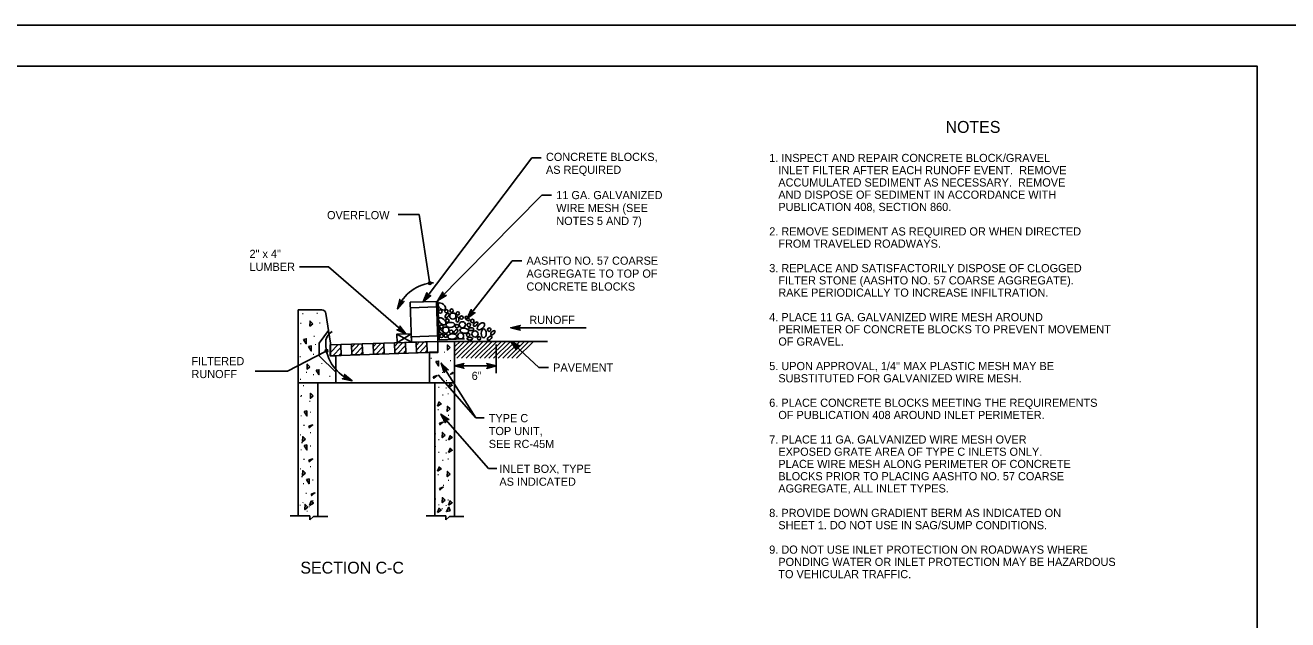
# Model space of a CAD drawing. Extents: x 636183 to 639890, y 299162 to 300538.
# Drawn here: x 637676.7 to 638140.2, y 300320 to 300538.4 of the extents above; entities that cross this region are included whole.
import ezdxf

# ---------------------------------------------------------------- set-up
doc = ezdxf.new("R2010")
doc.units = 0
for name, color, linetype in [('1', 7, 'Continuous'), ('Default', 7, 'Continuous'), ('PLT-BNDY', 7, 'Continuous')]:
    doc.layers.add(name, color=color, linetype=linetype)

# ---------------------------------------------------------------- blocks, each defined once
blk = doc.blocks.new('SC9446')
at = {"layer": 'Default'}
blk.add_line((0, 0), (0, 0), dxfattribs=at)

msp = doc.modelspace()

# ---------------------------------------------------------------- linework, layer by layer
at = {"layer": '1'}
msp.add_lwpolyline([(638128.91, 299959.45), (638128.91, 300523.45), (637342.91, 300523.45), (637342.91, 299959.45), (638128.91, 299959.45), (638128.91, 299985.81), (637928.91, 299985.81), (637928.91, 300050.49), (638128.91, 300050.49), (638128.91, 300079.45), (637928.91, 300079.45), (637928.91, 299959.45), (638007.72, 299959.45), (638007.72, 299985.81), (638007.72, 299959.45), (638084.72, 299959.45), (638084.72, 299985.81), (638084.72, 299973.49), (638128.91, 299973.49)], dxfattribs=at)
at = {"layer": 'Default'}
for p, q in [((637822.84, 300436.83), (637862.62, 300489.75)), ((637866.12, 300489.75), (637862.62, 300489.75)), ((637828.18, 300437.25), (637866.4, 300476.04)), ((637869.9, 300476.04), (637866.4, 300476.04)), ((637813.6, 300468.88), (637821.36, 300468.88)), ((637821.36, 300468.88), (637825.14, 300444.17)), ((637777.33, 300449.7), (637787.97, 300449.7)), ((637816.37, 300425), (637787.97, 300449.7)), ((637838.96, 300430.69), (637855.46, 300451.94)), ((637858.96, 300451.94), (637855.46, 300451.94)), ((637827.75, 300434.97), (637818.06, 300434.67)), ((637828.18, 300437.25), (637828.67, 300422.8)), ((637776.95, 300407.1), (637776.95, 300433.84)), ((637776.95, 300433.84), (637785.57, 300433.84)), ((637787.08, 300432.54), (637788.72, 300421.61)), ((637784.59, 300421.61), (637788.03, 300426.24)), ((637788.03, 300426.24), (637788.03, 300426.24)), ((637784.59, 300421.61), (637784.59, 300417.03)), ((637788.59, 300421.03), (637828.15, 300422.29)), ((637788.69, 300418.06), (637791.56, 300421.13)), ((637788.72, 300421.61), (637788.72, 300417.03)), ((637796.53, 300419.98), (637797.8, 300421.33)), ((637796.58, 300418.31), (637799.46, 300421.38)), ((637804.43, 300420.23), (637805.69, 300421.58)), ((637804.48, 300418.56), (637807.36, 300421.63)), ((637812.33, 300420.48), (637813.59, 300421.83)), ((637812.38, 300418.81), (637815.26, 300421.88)), ((637813.1, 300424.89), (637818.46, 300421.98)), ((637818.36, 300425.06), (637813.2, 300421.81)), ((637813.48, 300417.82), (637816.27, 300420.79)), ((637828.09, 300424.3), (637818.4, 300423.99)), ((637820.23, 300420.73), (637821.49, 300422.08)), ((637820.28, 300419.06), (637823.16, 300422.13)), ((637821.38, 300418.07), (637824.17, 300421.04)), ((637828.67, 300422.8), (637837.98, 300423.18)), ((637834.26, 300422.29), (637868.43, 300422.29)), ((637834.58, 300417.17), (637839.7, 300422.29)), ((637834.58, 300418.85), (637838.01, 300422.29)), ((637834.58, 300420.54), (637836.33, 300422.29)), ((637835.17, 300416.07), (637841.39, 300422.29)), ((637836.86, 300416.07), (637843.08, 300422.29)), ((637838.55, 300416.07), (637844.77, 300422.29)), ((637840.23, 300416.07), (637846.46, 300422.29)), ((637841.92, 300416.07), (637848.15, 300422.29)), ((637843.61, 300416.07), (637849.83, 300422.29)), ((637845.26, 300416.07), (637851.48, 300422.29)), ((637846.94, 300416.07), (637853.17, 300422.29)), ((637848.63, 300416.07), (637854.85, 300422.29)), ((637849.62, 300421.16), (637849.62, 300410.55)), ((637850.32, 300416.07), (637856.54, 300422.29)), ((637852.01, 300416.07), (637858.23, 300422.29)), ((637853.7, 300416.07), (637859.92, 300422.29)), ((637854.93, 300422.29), (637865.25, 300412.69)), ((637855.39, 300416.07), (637861.61, 300422.29)), ((637857.08, 300416.07), (637863.3, 300422.29)), ((637786.9, 300418.59), (637772.96, 300411.33)), ((637784.59, 300417.03), (637790.71, 300410.92)), ((637788.72, 300417.03), (637828.15, 300418.28)), ((637789.78, 300417.06), (637792.58, 300420.04)), ((637790.71, 300410.92), (637790.71, 300417.03)), ((637791.88, 300417.13), (637792.64, 300417.95)), ((637797.68, 300417.31), (637800.47, 300420.29)), ((637799.77, 300417.38), (637800.54, 300418.2)), ((637805.58, 300417.56), (637808.37, 300420.54)), ((637807.67, 300417.63), (637808.44, 300418.45)), ((637815.57, 300417.88), (637816.34, 300418.7)), ((637823.47, 300418.13), (637824.24, 300418.95)), ((637829.41, 300414.29), (637842.14, 300394.17)), ((637868.75, 300412.69), (637865.25, 300412.69)), ((637761.13, 300411.3), (637772.96, 300411.33)), ((637790.71, 300407.1), (637776.95, 300407.1)), ((637776.95, 300358.4), (637776.95, 300407.1)), ((637784.12, 300358.11), (637784.12, 300407.1)), ((637790.71, 300410.92), (637790.71, 300407.1)), ((637790.71, 300407.1), (637825.09, 300407.1)), ((637827.1, 300358.4), (637827.1, 300407.1)), ((637828.3, 300410.01), (637842.14, 300394.17)), ((637829.29, 300395.58), (637846.79, 300375.56)), ((637845.14, 300394.17), (637842.14, 300394.17)), ((637777.91, 300387.97), (637777.74, 300387.91)), ((637777.91, 300375.5), (637777.74, 300375.45)), ((637849.79, 300375.56), (637846.79, 300375.56)), ((637778.75, 300363.04), (637778.58, 300362.98)), ((637773.97, 300358.21), (637781.14, 300358.21)), ((637781.14, 300358.21), (637781.14, 300356.71)), ((637781.14, 300356.71), (637782.51, 300357.92)), ((637782.51, 300357.92), (637787.76, 300357.92)), ((637831.06, 300358.21), (637831.06, 300356.71)), ((637831.06, 300356.71), (637832.44, 300357.92)), ((637832.44, 300357.92), (637837.69, 300357.92))]:
    msp.add_line(p, q, dxfattribs=at)
for points in [[(637825.25, 300439.07), (637825.59, 300439.16), (637822.84, 300436.83), (637825.25, 300439.07), (637824.83, 300439.13), (637822.84, 300436.83), (637824.4, 300439.43), (637824.2, 300439.8), (637822.84, 300436.83), (637824.16, 300440.18), (637824.2, 300439.8)], [(637830.89, 300439.13), (637831.24, 300439.17), (637828.18, 300437.25), (637830.89, 300439.13), (637830.49, 300439.25), (637828.18, 300437.25), (637830.11, 300439.61), (637829.96, 300440), (637828.18, 300437.25), (637829.98, 300440.38), (637829.96, 300440)], [(637815.41, 300436.82), (637815.73, 300436.96), (637813.39, 300434.21), (637815.41, 300436.82), (637814.99, 300436.81), (637813.39, 300434.21), (637814.52, 300437.04), (637814.26, 300437.37), (637813.39, 300434.21), (637814.16, 300437.73), (637814.26, 300437.37)], [(637841.48, 300432.8), (637841.83, 300432.87), (637838.96, 300430.69), (637841.48, 300432.8), (637841.07, 300432.88), (637838.96, 300430.69), (637840.66, 300433.21), (637840.48, 300433.59), (637838.96, 300430.69), (637840.46, 300433.96), (637840.48, 300433.59)], [(637814.31, 300427.56), (637814.24, 300427.9), (637816.37, 300425), (637814.31, 300427.56), (637814.22, 300427.15), (637816.37, 300425), (637813.89, 300426.74), (637813.5, 300426.57), (637816.37, 300425), (637813.13, 300426.56), (637813.5, 300426.57)], [(637858.18, 300426.63), (637858.45, 300426.41), (637854.95, 300427.27), (637858.18, 300426.63), (637857.98, 300427), (637854.95, 300427.27), (637857.98, 300427.53), (637858.16, 300427.9), (637854.95, 300427.27), (637858.44, 300428.16), (637858.16, 300427.9)], [(637854.95, 300427.27), (637882.64, 300427.26)], [(637825.15, 300418.23), (637828.21, 300418.23), (637828.21, 300421.29)], [(637828.12, 300421.25), (637828.21, 300418.28)], [(637856.89, 300419.64), (637856.94, 300419.3), (637854.93, 300422.29), (637856.89, 300419.64), (637857, 300420.05), (637854.93, 300422.29), (637857.35, 300420.44), (637857.73, 300420.6), (637854.93, 300422.29), (637858.11, 300420.6), (637857.73, 300420.6)], [(637790.71, 300417.02), (637788.63, 300417.02), (637788.63, 300420.08)], [(637830.57, 300411.21), (637830.52, 300410.86), (637829.41, 300414.29), (637830.57, 300411.21), (637830.78, 300411.57), (637829.41, 300414.29), (637831.22, 300411.86), (637831.64, 300411.9), (637829.41, 300414.29), (637832, 300411.79), (637831.64, 300411.9)], [(637837.5, 300412.62), (637837.77, 300412.4), (637834.26, 300413.26), (637837.5, 300412.62), (637837.3, 300412.99), (637834.26, 300413.26), (637837.29, 300413.52), (637837.48, 300413.89), (637834.26, 300413.26), (637837.76, 300414.15), (637837.48, 300413.89)], [(637849.62, 300413.26), (637834.26, 300413.26)], [(637846.39, 300413.9), (637846.12, 300414.12), (637849.62, 300413.26), (637846.39, 300413.9), (637846.58, 300413.52), (637849.62, 300413.26), (637846.59, 300413), (637846.41, 300412.62), (637849.62, 300413.26), (637846.12, 300412.37), (637846.41, 300412.62)], [(637794.04, 300409.81), (637793.9, 300410.13), (637796.67, 300407.82), (637794.04, 300409.81), (637794.06, 300409.39), (637796.67, 300407.82), (637793.83, 300408.92), (637793.5, 300408.66), (637796.67, 300407.82), (637793.14, 300408.55), (637793.5, 300408.66)], [(637834.26, 300407.1), (637834.26, 300358.11)], [(637830.94, 300392.74), (637830.95, 300392.39), (637829.29, 300395.58), (637830.94, 300392.74), (637831.09, 300393.13), (637829.29, 300395.58), (637831.48, 300393.48), (637831.89, 300393.59), (637829.29, 300395.58), (637832.26, 300393.55), (637831.89, 300393.59)], [(637831.06, 300358.21), (637823.9, 300358.21)]]:
    msp.add_lwpolyline(points, dxfattribs=at)
for points in [[(637817.99, 300436.67), (637818.46, 300421.98), (637828.15, 300422.29), (637827.68, 300436.98)], [(637782.23, 300428.78), (637781.2, 300427.89), (637781.25, 300429.74)], [(637778.85, 300423), (637779.85, 300423.23), (637779.88, 300421.4)], [(637788.59, 300421.03), (637788.72, 300417.03), (637792.67, 300417.15), (637792.54, 300421.16)], [(637796.49, 300421.28), (637796.62, 300417.28), (637800.57, 300417.41), (637800.44, 300421.41)], [(637804.39, 300421.53), (637804.52, 300417.53), (637808.46, 300417.66), (637808.34, 300421.66)], [(637812.29, 300421.79), (637812.41, 300417.78), (637816.36, 300417.91), (637816.24, 300421.91)], [(637818.46, 300421.98), (637818.36, 300425.06), (637813.1, 300424.89), (637813.2, 300421.81)], [(637820.18, 300422.04), (637820.31, 300418.03), (637824.26, 300418.16), (637824.13, 300422.16)], [(637834.26, 300407.1), (637825.09, 300407.1), (637825.09, 300418.28), (637828.15, 300418.28), (637828.15, 300422.29), (637834.26, 300422.29)], [(637832.7, 300419.99), (637831.67, 300419.1), (637831.71, 300420.96)], [(637780.67, 300420.37), (637781.67, 300420.6), (637781.7, 300418.77)], [(637781.22, 300412.99), (637780.19, 300412.1), (637780.24, 300413.95)], [(637783.5, 300411.66), (637784.5, 300411.89), (637784.53, 300410.07)], [(637827.42, 300414.84), (637828.41, 300415.07), (637828.45, 300413.25)], [(637826.44, 300409.3), (637826.68, 300408.74), (637827.86, 300409.77)], [(637832.09, 300405.33), (637833.47, 300406.19), (637832.69, 300406.89)], [(637832.09, 300405.33), (637833.47, 300406.19), (637832.69, 300406.89)], [(637833.8, 300410.54), (637833.64, 300410.91), (637832.85, 300410.23)], [(637782.44, 300402.26), (637781.4, 300401.37), (637781.45, 300403.22)], [(637828.06, 300398.46), (637829.43, 300399.32), (637828.65, 300400.02)], [(637828.06, 300398.46), (637829.43, 300399.32), (637828.65, 300400.02)], [(637832.65, 300397.45), (637831.62, 300396.56), (637831.66, 300398.41)], [(637832.65, 300397.45), (637831.62, 300396.56), (637831.66, 300398.41)], [(637779.05, 300396.48), (637780.05, 300396.71), (637780.08, 300394.88)], [(637780.8, 300391.09), (637781.04, 300390.55), (637782.22, 300391.57)], [(637828.73, 300392.18), (637828.97, 300391.63), (637830.15, 300392.65)], [(637828.73, 300392.18), (637828.97, 300391.63), (637830.15, 300392.65)], [(637830.82, 300387.86), (637829.79, 300386.96), (637829.84, 300388.82)], [(637830.82, 300387.86), (637829.79, 300386.96), (637829.84, 300388.82)], [(637779.57, 300386.34), (637778.54, 300385.44), (637778.59, 300387.3)], [(637779.05, 300384.01), (637780.05, 300384.24), (637780.08, 300382.42)], [(637832.09, 300386.07), (637833.47, 300386.93), (637832.69, 300387.63)], [(637832.09, 300386.07), (637833.47, 300386.93), (637832.69, 300387.63)], [(637780.8, 300378.63), (637781.04, 300378.08), (637782.22, 300379.1)], [(637832.09, 300381.4), (637833.47, 300382.26), (637832.69, 300382.96)], [(637832.09, 300381.4), (637833.47, 300382.26), (637832.69, 300382.96)], [(637832.09, 300381.4), (637833.47, 300382.26), (637832.69, 300382.96)], [(637779.57, 300373.87), (637778.54, 300372.97), (637778.59, 300374.83)], [(637828.06, 300374.54), (637829.43, 300375.4), (637828.65, 300376.09)], [(637828.06, 300374.54), (637829.43, 300375.4), (637828.65, 300376.09)], [(637828.06, 300374.54), (637829.43, 300375.4), (637828.65, 300376.09)], [(637832.65, 300373.52), (637831.62, 300372.63), (637831.66, 300374.49)], [(637832.65, 300373.52), (637831.62, 300372.63), (637831.66, 300374.49)], [(637832.65, 300373.52), (637831.62, 300372.63), (637831.66, 300374.49)], [(637779.89, 300371.54), (637780.89, 300371.77), (637780.92, 300369.95)], [(637781.63, 300366.16), (637781.87, 300365.61), (637783.05, 300366.63)], [(637828.73, 300368.25), (637828.97, 300367.7), (637830.15, 300368.73)], [(637828.73, 300368.25), (637828.97, 300367.7), (637830.15, 300368.73)], [(637828.73, 300368.25), (637828.97, 300367.7), (637830.15, 300368.73)], [(637780.41, 300361.4), (637779.38, 300360.51), (637779.42, 300362.36)], [(637781.1, 300362.02), (637782.48, 300362.88), (637781.7, 300363.58)], [(637828.06, 300359.42), (637829.43, 300360.28), (637828.65, 300360.98)], [(637830.82, 300363.93), (637829.79, 300363.03), (637829.84, 300364.89)], [(637830.82, 300363.93), (637829.79, 300363.03), (637829.84, 300364.89)], [(637830.82, 300363.93), (637829.79, 300363.03), (637829.84, 300364.89)], [(637832.64, 300360.01), (637831.3, 300359.75), (637832.26, 300361.34)], [(637832.09, 300362.14), (637833.47, 300363), (637832.69, 300363.7)], [(637832.09, 300362.14), (637833.47, 300363), (637832.69, 300363.7)], [(637832.09, 300362.14), (637833.47, 300363), (637832.69, 300363.7)]]:
    msp.add_lwpolyline(points, close=True, dxfattribs=at)
for centre, radius in [((637825.21, 300443.7), 0.481), ((637829.08, 300433.25), 0.63), ((637831.31, 300433.35), 0.63), ((637831.66, 300429.92), 0.63), ((637833.68, 300431.56), 1.14), ((637833.21, 300433.56), 0.63), ((637835.48, 300432.57), 0.63), ((637836.84, 300431.03), 0.63), ((637840.84, 300429.79), 0.63), ((637829.52, 300427.69), 0.63), ((637831.11, 300426.42), 1.14), ((637833.06, 300425.78), 0.63), ((637835.17, 300427.89), 0.63), ((637836.5, 300424.3), 1.14), ((637837.15, 300428.38), 1.14), ((637839.54, 300428.32), 0.63), ((637841.84, 300424.98), 1.14), ((637847.05, 300426.6), 0.63), ((637829.52, 300424.3), 0.63), ((637831.05, 300424.36), 0.63), ((637839.31, 300424.67), 0.63), ((637843.31, 300423.43), 0.63), ((637787.32, 300418.82), 0.481)]:
    msp.add_circle(centre, radius, dxfattribs=at)
for centre, radius, start, end in [((637827.39, 300428.88), 14.98, 93.095, 159.1494), ((637785.57, 300432.31), 1.53, 8.5302, 90), ((637791.53, 300421.91), 4.53, 117.9934, 185.7686), ((637801.99, 300421.82), 14.98, 181.3993, 249.1745)]:
    msp.add_arc(centre, radius, start, end, dxfattribs=at)
for centre, major_axis, ratio in [((637829.64, 300435.1), (1.2, -1.12), 0.565936), ((637829.78, 300429.68), (1.2, -1.12), 0.565936), ((637831.58, 300431.76), (0.688, 0.736), 0.5), ((637835.37, 300430.36), (-0.03, 1.01), 0.5), ((637838.96, 300430.69), (-0.692, 0.731), 0.5), ((637829.38, 300425.85), (-0.727, 0.697), 0.5), ((637832.79, 300428.35), (1.64, 0.05), 0.565936), ((637834.77, 300425.83), (0.688, 0.736), 0.5), ((637837.91, 300426.19), (1.62, -0.21), 0.565936), ((637840.38, 300426.78), (-1.01, 0.03), 0.5), ((637842.03, 300428.64), (0.731, 0.692), 0.5), ((637843.98, 300427.81), (1.19, 1.13), 0.565936), ((637845.03, 300425.2), (-0.04, -1.64), 0.565936), ((637848.37, 300425.45), (0.731, 0.692), 0.5), ((637833.46, 300424.08), (1.64, 0.05), 0.565936), ((637839.9, 300423.27), (-1.01, 0.03), 0.5), ((637847.18, 300423.46), (0.731, 0.692), 0.5)]:
    msp.add_ellipse(centre, major_axis=major_axis, ratio=ratio, start_param=0, end_param=6.283175, dxfattribs=at)
at = {"layer": 'PLT-BNDY'}
msp.add_lwpolyline([(637302.91, 300538.45), (638143.91, 300538.45), (638143.91, 299944.45), (637302.91, 299944.45)], close=True, dxfattribs=at)

# ---------------------------------------------------------------- block references
at = {"layer": 'Default', "xscale": 3.24063778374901, "yscale": 3.2406377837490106, "rotation": 1.818570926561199}
for p in [(637816.27, 300420.87), (637820.22, 300420.99), (637824.17, 300421.12), (637828.12, 300421.25), (637792.57, 300420.12), (637796.52, 300420.24), (637800.47, 300420.37), (637804.42, 300420.49), (637808.37, 300420.62), (637812.32, 300420.74)]:
    msp.add_blockref('SC9446', p, dxfattribs=at)

# ---------------------------------------------------------------- texts
at = {"layer": 'Default'}
for s, height, p in [('NOTES', 4.372, (638014.56, 300498.9)), ('CONCRETE BLOCKS,', 2.998, (637867.86, 300488.58)), ('1. INSPECT AND REPAIR CONCRETE BLOCK/GRAVEL', 2.998, (637949.82, 300488.18)), ('AS REQUIRED', 2.998, (637867.86, 300483.84)), ('   INLET FILTER AFTER EACH RUNOFF EVENT.  REMOVE', 2.998, (637949.82, 300483.68)), ('   ACCUMULATED SEDIMENT AS NECESSARY.  REMOVE', 2.998, (637949.82, 300479.18)), ('11 GA. GALVANIZED', 2.998, (637871.65, 300474.54)), ('   AND DISPOSE OF SEDIMENT IN ACCORDANCE WITH', 2.998, (637949.82, 300474.69)), ('WIRE MESH (SEE', 2.998, (637871.65, 300469.8)), ('   PUBLICATION 408, SECTION 860.', 2.998, (637949.82, 300470.19)), ('OVERFLOW', 2.998, (637787.49, 300467.18)), ('NOTES 5 AND 7)', 2.998, (637871.65, 300465.05)), ('2. REMOVE SEDIMENT AS REQUIRED OR WHEN DIRECTED', 2.998, (637949.82, 300461.19)), ('   FROM TRAVELED ROADWAYS.', 2.998, (637949.82, 300456.7)), ('2" x 4"', 2.998, (637759.02, 300452.95)), ('AASHTO NO. 57 COARSE', 2.998, (637860.71, 300450.44)), ('LUMBER', 2.998, (637759.02, 300448.2)), ('AGGREGATE TO TOP OF', 2.998, (637860.71, 300445.69)), ('3. REPLACE AND SATISFACTORILY DISPOSE OF CLOGGED', 2.998, (637949.82, 300447.7)), ('CONCRETE BLOCKS', 2.998, (637860.71, 300440.94)), ('   FILTER STONE (AASHTO NO. 57 COARSE AGGREGATE).', 2.998, (637949.82, 300443.21)), ('   RAKE PERIODICALLY TO INCREASE INFILTRATION.', 2.998, (637949.82, 300438.71)), ('RUNOFF', 2.998, (637861.74, 300428.69)), ('4. PLACE 11 GA. GALVANIZED WIRE MESH AROUND', 2.998, (637949.82, 300429.71)), ('   PERIMETER OF CONCRETE BLOCKS TO PREVENT MOVEMENT', 2.998, (637949.82, 300425.22)), ('   OF GRAVEL. ', 2.998, (637949.82, 300420.72)), ('FILTERED', 2.998, (637737.72, 300413.54)), ('RUNOFF', 2.998, (637737.72, 300408.79)), ('PAVEMENT', 2.998, (637870.5, 300411.19)), ('5. UPON APPROVAL, 1/4" MAX PLASTIC MESH MAY BE', 2.998, (637949.82, 300411.73)), ('6"', 2.998, (637840.58, 300408.12)), ('   SUBSTITUTED FOR GALVANIZED WIRE MESH.', 2.998, (637949.82, 300407.23)), ('6. PLACE CONCRETE BLOCKS MEETING THE REQUIREMENTS', 2.998, (637949.82, 300398.24)), ('TYPE C', 2.998, (637846.86, 300392.59)), ('   OF PUBLICATION 408 AROUND INLET PERIMETER. ', 2.998, (637949.82, 300393.74)), ('TOP UNIT,', 2.998, (637846.86, 300387.85)), ('SEE RC-45M', 2.998, (637846.86, 300383.1)), ('7. PLACE 11 GA. GALVANIZED WIRE MESH OVER ', 2.998, (637949.82, 300384.74)), ('   EXPOSED GRATE AREA OF TYPE C INLETS ONLY.', 2.998, (637949.82, 300380.25)), ('INLET BOX, TYPE', 2.998, (637850.76, 300373.98)), ('   PLACE WIRE MESH ALONG PERIMETER OF CONCRETE', 2.998, (637949.82, 300375.75)), ('AS INDICATED', 2.998, (637850.76, 300369.23)), ('   AGGREGATE, ALL INLET TYPES.', 2.998, (637949.82, 300366.76)), ('   BLOCKS PRIOR TO PLACING AASHTO NO. 57 COARSE', 2.998, (637949.82, 300371.25)), ('8. PROVIDE DOWN GRADIENT BERM AS INDICATED ON ', 2.998, (637949.82, 300357.76)), ('   SHEET 1. DO NOT USE IN SAG/SUMP CONDITIONS.', 2.998, (637949.82, 300353.26)), ('9. DO NOT USE INLET PROTECTION ON ROADWAYS WHERE', 2.998, (637949.82, 300344.27)), ('   PONDING WATER OR INLET PROTECTION MAY BE HAZARDOUS', 2.998, (637949.82, 300339.77)), ('SECTION C-C', 4.3721, (637777.71, 300336.96)), ('   TO VEHICULAR TRAFFIC.', 2.998, (637949.82, 300335.28))]:
    msp.add_text(s, height=height, dxfattribs=at).set_placement(p)
for p in [(637779.14, 300432.72), (637784.42, 300432.79), (637778.4, 300429.12), (637785.44, 300429.29), (637778.36, 300421.66), (637783.33, 300424.33), (637783.79, 300421.38), (637778.13, 300416.92), (637783.06, 300417.78), (637826.31, 300416.25), (637831.11, 300418.55), (637786.16, 300414.37), (637833.4, 300415.42), (637778.33, 300408.55), (637780.5, 300411.17), (637783.01, 300410.32), (637789.05, 300409.64), (637830.38, 300411.08), (637831.94, 300408.11), (637778.36, 300402.36), (637778.61, 300402.6), (637779.34, 300406.2), (637829.13, 300405.65), (637829.13, 300405.65), (637830.54, 300402.78), (637830.54, 300402.78), (637831.73, 300405.4), (637831.73, 300405.4), (637832.48, 300403.25), (637832.48, 300403.25), (637781.71, 300400.44), (637778.56, 300395.14), (637781.95, 300396.51), (637828.84, 300397.43), (637828.84, 300397.43), (637830.79, 300393.51), (637830.79, 300393.51), (637832.67, 300395.37), (637832.67, 300395.37), (637779.58, 300391.63), (637781.95, 300388.93), (637827.87, 300388.55), (637827.87, 300388.55), (637778.84, 300385.26), (637781.95, 300384.04), (637827.87, 300383.88), (637827.87, 300383.88), (637827.87, 300383.88), (637829.13, 300386.4), (637829.13, 300386.4), (637831.73, 300386.14), (637831.73, 300386.14), (637778.56, 300382.67), (637779.58, 300379.16), (637829.13, 300381.72), (637829.13, 300381.72), (637829.13, 300381.72), (637831.73, 300381.47), (637831.73, 300381.47), (637831.73, 300381.47), (637832.48, 300379.32), (637832.48, 300379.32), (637832.48, 300379.32), (637781.95, 300376.46), (637830.54, 300378.85), (637830.54, 300378.85), (637830.54, 300378.85), (637778.84, 300372.79), (637779.4, 300370.2), (637782.78, 300371.58), (637828.84, 300373.5), (637828.84, 300373.5), (637828.84, 300373.5), (637832.67, 300371.44), (637832.67, 300371.44), (637832.67, 300371.44), (637780.41, 300366.7), (637830.79, 300369.59), (637830.79, 300369.59), (637830.79, 300369.59), (637778.14, 300362.34), (637781.43, 300361.72), (637782.78, 300364), (637827.87, 300364.62), (637827.87, 300364.62), (637827.87, 300364.62), (637829.13, 300362.47), (637829.13, 300362.47), (637829.13, 300362.47), (637830.33, 300361.02), (637831.73, 300362.21), (637831.73, 300362.21), (637831.73, 300362.21), (637832.48, 300364.2), (637780.79, 300360.14)]:
    msp.add_text('.', height=2.94, rotation=180, dxfattribs=at).set_placement(p)

doc.saveas('drawing.dxf')
